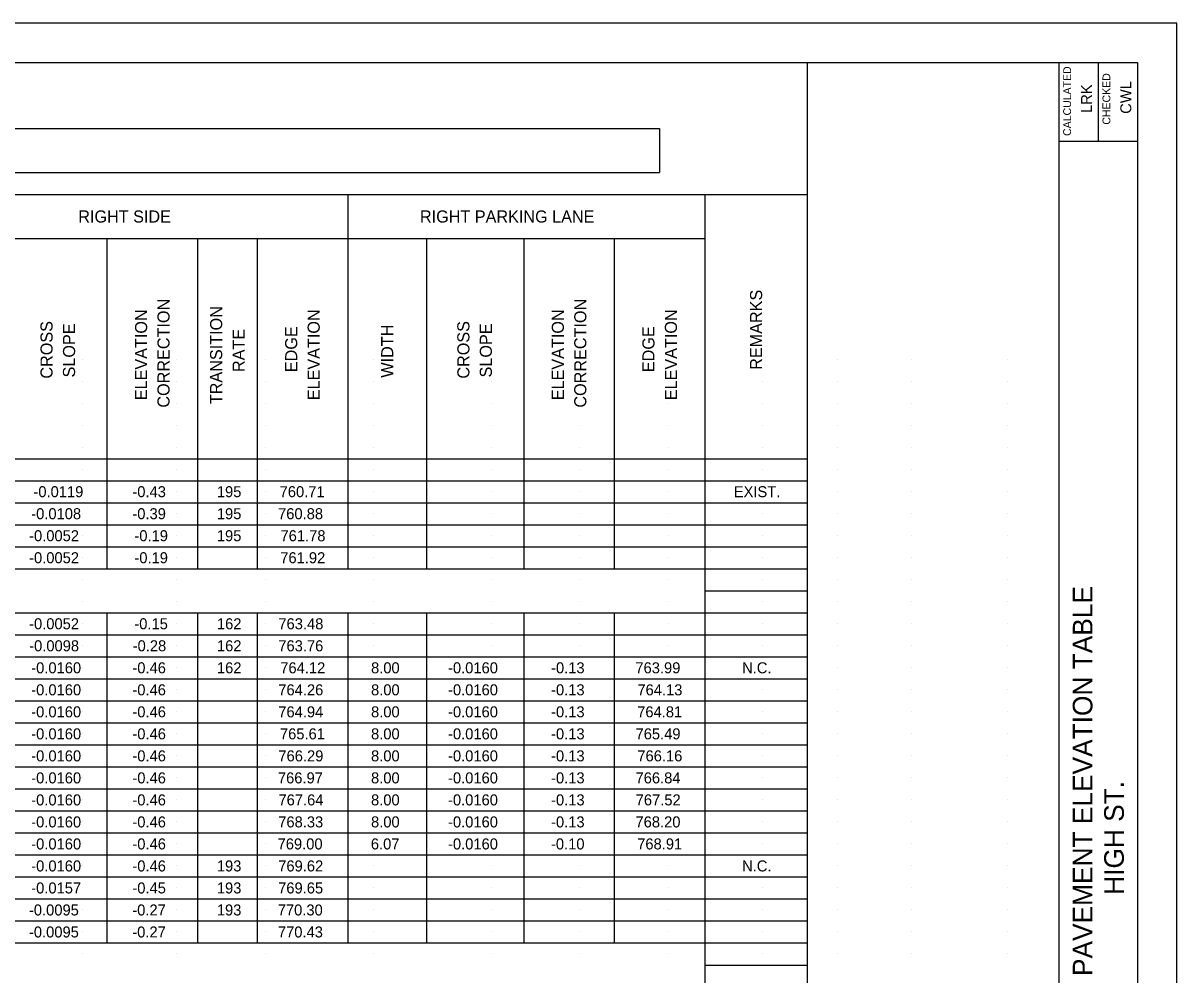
# Model space of a CAD drawing. Extents: x -15.4 to 18.6, y -12.6 to 9.4.
# Drawn here: x 3.96 to 18.64, y -2.72 to 9.39 of the extents above; entities that cross this region are included whole.
import ezdxf

# ---------------------------------------------------------------- set-up
doc = ezdxf.new("R2010")
doc.units = 0
for name, color, linetype in [('SH_Border', 7, 'Continuous'), ('SH_Cut_Line', 7, 'Continuous'), ('SH_Data', 7, 'Continuous'), ('SH_Text', 7, 'Continuous')]:
    doc.layers.add(name, color=color, linetype=linetype)

msp = doc.modelspace()

# ---------------------------------------------------------------- linework, layer by layer
at = {"layer": 'SH_Border'}
for p, q in [((17.143, -12.112), (17.143, 8.888)), ((17.643, 8.888), (17.643, 7.888)), ((17.143, 7.888), (18.143, 7.888))]:
    msp.add_line(p, q, dxfattribs=at)
msp.add_lwpolyline([(-13.357, 8.888), (18.143, 8.888), (18.143, -12.112), (-13.357, -12.112)], close=True, dxfattribs=at)
at = {"layer": 'SH_Cut_Line'}
msp.add_lwpolyline([(-15.357, -12.612), (18.643, -12.612), (18.643, 9.388), (-15.357, 9.388)], close=True, dxfattribs=at)
at = {"layer": 'SH_Data'}
for p, q in [((-10.059, 8.888), (13.939, 8.888)), ((13.939, 8.888), (13.939, -6.232)), ((-8.906, 8.048), (12.061, 8.048)), ((12.061, 8.048), (12.061, 7.488)), ((-8.906, 7.488), (12.061, 7.488)), ((-10.059, 7.208), (13.939, 7.208)), ((8.092, 7.208), (8.092, 2.448)), ((12.637, 7.208), (12.637, -6.232)), ((-10.059, 6.648), (12.637, 6.648)), ((5.028, 6.648), (5.028, 2.448)), ((6.181, 6.648), (6.181, 2.448)), ((6.939, 6.648), (6.939, 2.448)), ((9.096, 6.648), (9.096, 2.448)), ((10.332, 6.648), (10.332, 2.448)), ((11.484, 6.648), (11.484, 2.448)), ((4.718, 5.108), (4.718, 5.108)), ((5.918, 5.108), (5.918, 5.108)), ((7.043, 5.108), (7.043, 5.108)), ((8.418, 5.108), (8.418, 5.108)), ((9.918, 5.108), (9.918, 5.108)), ((11.043, 5.108), (11.043, 5.108)), ((12.168, 5.108), (12.168, 5.108)), ((13.368, 5.108), (13.368, 5.108)), ((14.318, 5.108), (14.318, 5.108)), ((15.268, 5.108), (15.268, 5.108)), ((16.493, 5.108), (16.493, 5.108)), ((4.718, 4.828), (4.718, 4.828)), ((5.918, 4.828), (5.918, 4.828)), ((7.043, 4.828), (7.043, 4.828)), ((8.418, 4.828), (8.418, 4.828)), ((9.918, 4.828), (9.918, 4.828)), ((11.043, 4.828), (11.043, 4.828)), ((12.168, 4.828), (12.168, 4.828)), ((13.368, 4.828), (13.368, 4.828)), ((14.318, 4.828), (14.318, 4.828)), ((15.268, 4.828), (15.268, 4.828)), ((16.493, 4.828), (16.493, 4.828)), ((4.718, 4.548), (4.718, 4.548)), ((5.918, 4.548), (5.918, 4.548)), ((7.043, 4.548), (7.043, 4.548)), ((8.418, 4.548), (8.418, 4.548)), ((9.918, 4.548), (9.918, 4.548)), ((11.043, 4.548), (11.043, 4.548)), ((12.168, 4.548), (12.168, 4.548)), ((13.368, 4.548), (13.368, 4.548)), ((14.318, 4.548), (14.318, 4.548)), ((15.268, 4.548), (15.268, 4.548)), ((16.493, 4.548), (16.493, 4.548)), ((4.718, 4.268), (4.718, 4.268)), ((5.918, 4.268), (5.918, 4.268)), ((7.043, 4.268), (7.043, 4.268)), ((8.418, 4.268), (8.418, 4.268)), ((9.918, 4.268), (9.918, 4.268)), ((11.043, 4.268), (11.043, 4.268)), ((12.168, 4.268), (12.168, 4.268)), ((13.368, 4.268), (13.368, 4.268)), ((14.318, 4.268), (14.318, 4.268)), ((15.268, 4.268), (15.268, 4.268)), ((16.493, 4.268), (16.493, 4.268)), ((4.718, 3.988), (4.718, 3.988)), ((5.918, 3.988), (5.918, 3.988)), ((7.043, 3.988), (7.043, 3.988)), ((8.418, 3.988), (8.418, 3.988)), ((9.918, 3.988), (9.918, 3.988)), ((11.043, 3.988), (11.043, 3.988)), ((12.168, 3.988), (12.168, 3.988)), ((13.368, 3.988), (13.368, 3.988)), ((14.318, 3.988), (14.318, 3.988)), ((15.268, 3.988), (15.268, 3.988)), ((16.493, 3.988), (16.493, 3.988)), ((-10.059, 3.848), (13.939, 3.848)), ((4.718, 3.708), (4.718, 3.708)), ((5.918, 3.708), (5.918, 3.708)), ((7.043, 3.708), (7.043, 3.708)), ((8.418, 3.708), (8.418, 3.708)), ((9.918, 3.708), (9.918, 3.708)), ((11.043, 3.708), (11.043, 3.708)), ((12.168, 3.708), (12.168, 3.708)), ((13.368, 3.708), (13.368, 3.708)), ((14.318, 3.708), (14.318, 3.708)), ((15.268, 3.708), (15.268, 3.708)), ((16.493, 3.708), (16.493, 3.708)), ((-10.059, 3.568), (13.939, 3.568)), ((4.718, 3.428), (4.718, 3.428)), ((5.918, 3.428), (5.918, 3.428)), ((7.043, 3.428), (7.043, 3.428)), ((8.418, 3.428), (8.418, 3.428)), ((9.918, 3.428), (9.918, 3.428)), ((11.043, 3.428), (11.043, 3.428)), ((12.168, 3.428), (12.168, 3.428)), ((13.368, 3.428), (13.368, 3.428)), ((14.318, 3.428), (14.318, 3.428)), ((15.268, 3.428), (15.268, 3.428)), ((16.493, 3.428), (16.493, 3.428)), ((-10.059, 3.288), (13.939, 3.288)), ((4.718, 3.148), (4.718, 3.148)), ((5.918, 3.148), (5.918, 3.148)), ((7.043, 3.148), (7.043, 3.148)), ((8.418, 3.148), (8.418, 3.148)), ((9.918, 3.148), (9.918, 3.148)), ((11.043, 3.148), (11.043, 3.148)), ((12.168, 3.148), (12.168, 3.148)), ((13.368, 3.148), (13.368, 3.148)), ((14.318, 3.148), (14.318, 3.148)), ((15.268, 3.148), (15.268, 3.148)), ((16.493, 3.148), (16.493, 3.148)), ((-10.059, 3.008), (13.939, 3.008)), ((4.718, 2.868), (4.718, 2.868)), ((5.918, 2.868), (5.918, 2.868)), ((7.043, 2.868), (7.043, 2.868)), ((8.418, 2.868), (8.418, 2.868)), ((9.918, 2.868), (9.918, 2.868)), ((11.043, 2.868), (11.043, 2.868)), ((12.168, 2.868), (12.168, 2.868)), ((13.368, 2.868), (13.368, 2.868)), ((14.318, 2.868), (14.318, 2.868)), ((15.268, 2.868), (15.268, 2.868)), ((16.493, 2.868), (16.493, 2.868)), ((-10.059, 2.728), (13.939, 2.728)), ((4.718, 2.588), (4.718, 2.588)), ((5.918, 2.588), (5.918, 2.588)), ((7.043, 2.588), (7.043, 2.588)), ((8.418, 2.588), (8.418, 2.588)), ((9.918, 2.588), (9.918, 2.588)), ((11.043, 2.588), (11.043, 2.588)), ((12.168, 2.588), (12.168, 2.588)), ((13.368, 2.588), (13.368, 2.588)), ((14.318, 2.588), (14.318, 2.588)), ((15.268, 2.588), (15.268, 2.588)), ((16.493, 2.588), (16.493, 2.588)), ((-10.059, 2.448), (13.939, 2.448)), ((4.718, 2.308), (4.718, 2.308)), ((5.918, 2.308), (5.918, 2.308)), ((7.043, 2.308), (7.043, 2.308)), ((8.418, 2.308), (8.418, 2.308)), ((9.918, 2.308), (9.918, 2.308)), ((11.043, 2.308), (11.043, 2.308)), ((12.168, 2.308), (12.168, 2.308)), ((13.368, 2.308), (13.368, 2.308)), ((14.318, 2.308), (14.318, 2.308)), ((15.268, 2.308), (15.268, 2.308)), ((16.493, 2.308), (16.493, 2.308)), ((12.637, 2.168), (13.939, 2.168)), ((4.718, 2.028), (4.718, 2.028)), ((5.918, 2.028), (5.918, 2.028)), ((7.043, 2.028), (7.043, 2.028)), ((8.418, 2.028), (8.418, 2.028)), ((9.918, 2.028), (9.918, 2.028)), ((11.043, 2.028), (11.043, 2.028)), ((12.168, 2.028), (12.168, 2.028)), ((13.368, 2.028), (13.368, 2.028)), ((14.318, 2.028), (14.318, 2.028)), ((15.268, 2.028), (15.268, 2.028)), ((16.493, 2.028), (16.493, 2.028)), ((-10.059, 1.888), (13.939, 1.888)), ((5.028, 1.888), (5.028, -2.312)), ((6.181, 1.888), (6.181, -2.312)), ((6.939, 1.888), (6.939, -2.312)), ((8.092, 1.888), (8.092, -2.312)), ((9.096, 1.888), (9.096, -2.312)), ((10.332, 1.888), (10.332, -2.312)), ((11.484, 1.888), (11.484, -2.312)), ((4.718, 1.748), (4.718, 1.748)), ((5.918, 1.748), (5.918, 1.748)), ((7.043, 1.748), (7.043, 1.748)), ((8.418, 1.748), (8.418, 1.748)), ((9.918, 1.748), (9.918, 1.748)), ((11.043, 1.748), (11.043, 1.748)), ((12.168, 1.748), (12.168, 1.748)), ((13.368, 1.748), (13.368, 1.748)), ((14.318, 1.748), (14.318, 1.748)), ((15.268, 1.748), (15.268, 1.748)), ((16.493, 1.748), (16.493, 1.748)), ((-10.059, 1.608), (13.939, 1.608)), ((-10.059, 1.328), (13.939, 1.328)), ((4.718, 1.468), (4.718, 1.468)), ((5.918, 1.468), (5.918, 1.468)), ((7.043, 1.468), (7.043, 1.468)), ((8.418, 1.468), (8.418, 1.468)), ((9.918, 1.468), (9.918, 1.468)), ((11.043, 1.468), (11.043, 1.468)), ((12.168, 1.468), (12.168, 1.468)), ((13.368, 1.468), (13.368, 1.468)), ((14.318, 1.468), (14.318, 1.468)), ((15.268, 1.468), (15.268, 1.468)), ((16.493, 1.468), (16.493, 1.468)), ((4.718, 1.188), (4.718, 1.188)), ((5.918, 1.188), (5.918, 1.188)), ((7.043, 1.188), (7.043, 1.188)), ((8.418, 1.188), (8.418, 1.188)), ((9.918, 1.188), (9.918, 1.188)), ((11.043, 1.188), (11.043, 1.188)), ((12.168, 1.188), (12.168, 1.188)), ((13.368, 1.188), (13.368, 1.188)), ((14.318, 1.188), (14.318, 1.188)), ((15.268, 1.188), (15.268, 1.188)), ((16.493, 1.188), (16.493, 1.188)), ((-10.059, 1.048), (13.939, 1.048)), ((4.718, 0.908), (4.718, 0.908)), ((5.918, 0.908), (5.918, 0.908)), ((7.043, 0.908), (7.043, 0.908)), ((8.418, 0.908), (8.418, 0.908)), ((9.918, 0.908), (9.918, 0.908)), ((11.043, 0.908), (11.043, 0.908)), ((12.168, 0.908), (12.168, 0.908)), ((13.368, 0.908), (13.368, 0.908)), ((14.318, 0.908), (14.318, 0.908)), ((15.268, 0.908), (15.268, 0.908)), ((16.493, 0.908), (16.493, 0.908)), ((-10.059, 0.768), (13.939, 0.768)), ((4.718, 0.628), (4.718, 0.628)), ((5.918, 0.628), (5.918, 0.628)), ((7.043, 0.628), (7.043, 0.628)), ((8.418, 0.628), (8.418, 0.628)), ((9.918, 0.628), (9.918, 0.628)), ((11.043, 0.628), (11.043, 0.628)), ((12.168, 0.628), (12.168, 0.628)), ((13.368, 0.628), (13.368, 0.628)), ((14.318, 0.628), (14.318, 0.628)), ((15.268, 0.628), (15.268, 0.628)), ((16.493, 0.628), (16.493, 0.628)), ((-10.059, 0.488), (13.939, 0.488)), ((4.718, 0.348), (4.718, 0.348)), ((5.918, 0.348), (5.918, 0.348)), ((7.043, 0.348), (7.043, 0.348)), ((8.418, 0.348), (8.418, 0.348)), ((9.918, 0.348), (9.918, 0.348)), ((11.043, 0.348), (11.043, 0.348)), ((12.168, 0.348), (12.168, 0.348)), ((13.368, 0.348), (13.368, 0.348)), ((14.318, 0.348), (14.318, 0.348)), ((15.268, 0.348), (15.268, 0.348)), ((16.493, 0.348), (16.493, 0.348)), ((-10.059, 0.208), (13.939, 0.208)), ((4.718, 0.068), (4.718, 0.068)), ((5.918, 0.068), (5.918, 0.068)), ((7.043, 0.068), (7.043, 0.068)), ((8.418, 0.068), (8.418, 0.068)), ((9.918, 0.068), (9.918, 0.068)), ((11.043, 0.068), (11.043, 0.068)), ((12.168, 0.068), (12.168, 0.068)), ((13.368, 0.068), (13.368, 0.068)), ((14.318, 0.068), (14.318, 0.068)), ((15.268, 0.068), (15.268, 0.068)), ((16.493, 0.068), (16.493, 0.068)), ((-10.059, -0.072), (13.939, -0.072)), ((4.718, -0.212), (4.718, -0.212)), ((5.918, -0.212), (5.918, -0.212)), ((7.043, -0.212), (7.043, -0.212)), ((8.418, -0.212), (8.418, -0.212)), ((9.918, -0.212), (9.918, -0.212)), ((11.043, -0.212), (11.043, -0.212)), ((12.168, -0.212), (12.168, -0.212)), ((13.368, -0.212), (13.368, -0.212)), ((14.318, -0.212), (14.318, -0.212)), ((15.268, -0.212), (15.268, -0.212)), ((16.493, -0.212), (16.493, -0.212)), ((-10.059, -0.352), (13.939, -0.352)), ((4.718, -0.492), (4.718, -0.492)), ((5.918, -0.492), (5.918, -0.492)), ((7.043, -0.492), (7.043, -0.492)), ((8.418, -0.492), (8.418, -0.492)), ((9.918, -0.492), (9.918, -0.492)), ((11.043, -0.492), (11.043, -0.492)), ((12.168, -0.492), (12.168, -0.492)), ((13.368, -0.492), (13.368, -0.492)), ((14.318, -0.492), (14.318, -0.492)), ((15.268, -0.492), (15.268, -0.492)), ((16.493, -0.492), (16.493, -0.492)), ((-10.059, -0.632), (13.939, -0.632)), ((4.718, -0.772), (4.718, -0.772)), ((5.918, -0.772), (5.918, -0.772)), ((7.043, -0.772), (7.043, -0.772)), ((8.418, -0.772), (8.418, -0.772)), ((9.918, -0.772), (9.918, -0.772)), ((11.043, -0.772), (11.043, -0.772)), ((12.168, -0.772), (12.168, -0.772)), ((13.368, -0.772), (13.368, -0.772)), ((14.318, -0.772), (14.318, -0.772)), ((15.268, -0.772), (15.268, -0.772)), ((16.493, -0.772), (16.493, -0.772)), ((-10.059, -0.912), (13.939, -0.912)), ((4.718, -1.052), (4.718, -1.052)), ((5.918, -1.052), (5.918, -1.052)), ((7.043, -1.052), (7.043, -1.052)), ((8.418, -1.052), (8.418, -1.052)), ((9.918, -1.052), (9.918, -1.052)), ((11.043, -1.052), (11.043, -1.052)), ((12.168, -1.052), (12.168, -1.052)), ((13.368, -1.052), (13.368, -1.052)), ((14.318, -1.052), (14.318, -1.052)), ((15.268, -1.052), (15.268, -1.052)), ((16.493, -1.052), (16.493, -1.052)), ((-10.059, -1.192), (13.939, -1.192)), ((4.718, -1.332), (4.718, -1.332)), ((5.918, -1.332), (5.918, -1.332)), ((7.043, -1.332), (7.043, -1.332)), ((8.418, -1.332), (8.418, -1.332)), ((9.918, -1.332), (9.918, -1.332)), ((11.043, -1.332), (11.043, -1.332)), ((12.168, -1.332), (12.168, -1.332)), ((13.368, -1.332), (13.368, -1.332)), ((14.318, -1.332), (14.318, -1.332)), ((15.268, -1.332), (15.268, -1.332)), ((16.493, -1.332), (16.493, -1.332)), ((-10.059, -1.472), (13.939, -1.472)), ((4.718, -1.612), (4.718, -1.612)), ((5.918, -1.612), (5.918, -1.612)), ((7.043, -1.612), (7.043, -1.612)), ((8.418, -1.612), (8.418, -1.612)), ((9.918, -1.612), (9.918, -1.612)), ((11.043, -1.612), (11.043, -1.612)), ((12.168, -1.612), (12.168, -1.612)), ((13.368, -1.612), (13.368, -1.612)), ((14.318, -1.612), (14.318, -1.612)), ((15.268, -1.612), (15.268, -1.612)), ((16.493, -1.612), (16.493, -1.612)), ((-10.059, -1.752), (13.939, -1.752)), ((4.718, -1.892), (4.718, -1.892)), ((5.918, -1.892), (5.918, -1.892)), ((7.043, -1.892), (7.043, -1.892)), ((8.418, -1.892), (8.418, -1.892)), ((9.918, -1.892), (9.918, -1.892)), ((11.043, -1.892), (11.043, -1.892)), ((12.168, -1.892), (12.168, -1.892)), ((13.368, -1.892), (13.368, -1.892)), ((14.318, -1.892), (14.318, -1.892)), ((15.268, -1.892), (15.268, -1.892)), ((16.493, -1.892), (16.493, -1.892)), ((-10.059, -2.032), (13.939, -2.032)), ((4.718, -2.172), (4.718, -2.172)), ((5.918, -2.172), (5.918, -2.172)), ((7.043, -2.172), (7.043, -2.172)), ((8.418, -2.172), (8.418, -2.172)), ((9.918, -2.172), (9.918, -2.172)), ((11.043, -2.172), (11.043, -2.172)), ((12.168, -2.172), (12.168, -2.172)), ((13.368, -2.172), (13.368, -2.172)), ((14.318, -2.172), (14.318, -2.172)), ((15.268, -2.172), (15.268, -2.172)), ((16.493, -2.172), (16.493, -2.172)), ((-10.059, -2.312), (13.939, -2.312)), ((4.718, -2.452), (4.718, -2.452)), ((5.918, -2.452), (5.918, -2.452)), ((7.043, -2.452), (7.043, -2.452)), ((8.418, -2.452), (8.418, -2.452)), ((9.918, -2.452), (9.918, -2.452)), ((11.043, -2.452), (11.043, -2.452)), ((12.168, -2.452), (12.168, -2.452)), ((13.368, -2.452), (13.368, -2.452)), ((14.318, -2.452), (14.318, -2.452)), ((15.268, -2.452), (15.268, -2.452)), ((16.493, -2.452), (16.493, -2.452)), ((12.637, -2.592), (13.939, -2.592))]:
    msp.add_line(p, q, dxfattribs=at)

# ---------------------------------------------------------------- texts
for s, height, p in [('CALCULATED', 0.1, (17.296, 7.953)), ('CHECKED', 0.1, (17.796, 8.096)), ('LRK', 0.14, (17.563, 8.245)), ('CWL', 0.14, (18.063, 8.234)), ('PAVEMENT ELEVATION TABLE', 0.25, (17.568, -2.732)), ('              HIGH ST.              ', 0.25, (17.968, -3))]:
    msp.add_text(s, height=height, rotation=90, dxfattribs=at).set_placement(p)
at = {"layer": 'SH_Text'}
for s, height, p in [('RIGHT SIDE ', 0.154, (4.663, 6.851)), ('RIGHT PARKING LANE', 0.154, (9.011, 6.851)), ('-0.0119', 0.14, (4.092, 3.358)), ('-0.43', 0.14, (5.351, 3.358)), ('195', 0.14, (6.426, 3.358)), ('760.71', 0.14, (7.225, 3.358)), ('EXIST.', 0.14, (13.004, 3.358)), ('-0.0108', 0.14, (4.064, 3.078)), ('-0.39', 0.14, (5.351, 3.078)), ('195', 0.14, (6.426, 3.078)), ('760.88', 0.14, (7.205, 3.078)), ('-0.0052', 0.14, (4.037, 2.798)), ('-0.19', 0.14, (5.377, 2.798)), ('195', 0.14, (6.426, 2.798)), ('761.78', 0.14, (7.236, 2.798)), ('-0.0052', 0.14, (4.037, 2.518)), ('-0.19', 0.14, (5.377, 2.518)), ('761.92', 0.14, (7.233, 2.518)), ('-0.0052', 0.14, (4.037, 1.678)), ('-0.15', 0.14, (5.376, 1.678)), ('162', 0.14, (6.427, 1.678)), ('763.48', 0.14, (7.209, 1.678)), ('-0.0098', 0.14, (4.038, 1.398)), ('-0.28', 0.14, (5.355, 1.398)), ('162', 0.14, (6.427, 1.398)), ('763.76', 0.14, (7.208, 1.398)), ('-0.0160', 0.14, (4.064, 1.118)), ('-0.46', 0.14, (5.351, 1.118)), ('162', 0.14, (6.427, 1.118)), ('764.12', 0.14, (7.233, 1.118)), ('8.00', 0.14, (8.388, 1.118)), ('-0.0160', 0.14, (9.368, 1.118)), ('-0.13', 0.14, (10.679, 1.118)), ('763.99', 0.14, (11.752, 1.118)), ('N.C.', 0.14, (13.11, 1.118)), ('-0.0160', 0.14, (4.064, 0.838)), ('-0.46', 0.14, (5.351, 0.838)), ('764.26', 0.14, (7.208, 0.838)), ('8.00', 0.14, (8.388, 0.838)), ('-0.0160', 0.14, (9.368, 0.838)), ('-0.13', 0.14, (10.679, 0.838)), ('764.13', 0.14, (11.778, 0.838)), ('-0.0160', 0.14, (4.064, 0.558)), ('-0.46', 0.14, (5.351, 0.558)), ('764.94', 0.14, (7.208, 0.558)), ('8.00', 0.14, (8.388, 0.558)), ('-0.0160', 0.14, (9.368, 0.558)), ('-0.13', 0.14, (10.679, 0.558)), ('764.81', 0.14, (11.775, 0.558)), ('-0.0160', 0.14, (4.064, 0.278)), ('-0.46', 0.14, (5.351, 0.278)), ('765.61', 0.14, (7.229, 0.278)), ('8.00', 0.14, (8.388, 0.278)), ('-0.0160', 0.14, (9.368, 0.278)), ('-0.13', 0.14, (10.679, 0.278)), ('765.49', 0.14, (11.754, 0.278)), ('-0.0160', 0.14, (4.064, -0.002)), ('-0.46', 0.14, (5.351, -0.002)), ('766.29', 0.14, (7.209, -0.002)), ('8.00', 0.14, (8.388, -0.002)), ('-0.0160', 0.14, (9.368, -0.002)), ('-0.13', 0.14, (10.679, -0.002)), ('766.16', 0.14, (11.777, -0.002)), ('-0.0160', 0.14, (4.064, -0.282)), ('-0.46', 0.14, (5.351, -0.282)), ('766.97', 0.14, (7.203, -0.282)), ('8.00', 0.14, (8.388, -0.282)), ('-0.0160', 0.14, (9.368, -0.282)), ('-0.13', 0.14, (10.679, -0.282)), ('766.84', 0.14, (11.754, -0.282)), ('-0.0160', 0.14, (4.064, -0.562)), ('-0.46', 0.14, (5.351, -0.562)), ('767.64', 0.14, (7.21, -0.562)), ('8.00', 0.14, (8.388, -0.562)), ('-0.0160', 0.14, (9.368, -0.562)), ('-0.13', 0.14, (10.679, -0.562)), ('767.52', 0.14, (11.756, -0.562)), ('-0.0160', 0.14, (4.064, -0.842)), ('-0.46', 0.14, (5.351, -0.842)), ('768.33', 0.14, (7.207, -0.842)), ('8.00', 0.14, (8.388, -0.842)), ('-0.0160', 0.14, (9.368, -0.842)), ('-0.13', 0.14, (10.679, -0.842)), ('768.20', 0.14, (11.753, -0.842)), ('-0.0160', 0.14, (4.064, -1.122)), ('-0.46', 0.14, (5.351, -1.122)), ('769.00', 0.14, (7.199, -1.122)), ('6.07', 0.14, (8.386, -1.122)), ('-0.0160', 0.14, (9.368, -1.122)), ('-0.10', 0.14, (10.678, -1.122)), ('768.91', 0.14, (11.775, -1.122)), ('-0.0160', 0.14, (4.064, -1.402)), ('-0.46', 0.14, (5.351, -1.402)), ('193', 0.14, (6.426, -1.402)), ('769.62', 0.14, (7.207, -1.402)), ('N.C.', 0.14, (13.11, -1.402)), ('-0.0157', 0.14, (4.064, -1.682)), ('-0.45', 0.14, (5.351, -1.682)), ('193', 0.14, (6.426, -1.682)), ('769.65', 0.14, (7.206, -1.682)), ('-0.0095', 0.14, (4.035, -1.962)), ('-0.27', 0.14, (5.35, -1.962)), ('193', 0.14, (6.426, -1.962)), ('770.30', 0.14, (7.201, -1.962)), ('-0.0095', 0.14, (4.035, -2.242)), ('-0.27', 0.14, (5.35, -2.242)), ('770.43', 0.14, (7.203, -2.242))]:
    msp.add_text(s, height=height, dxfattribs=at).set_placement(p)
for s, p in [('REMARKS', (13.365, 4.978)), ('ELEVATION', (5.539, 4.591)), ('CORRECTION', (5.824, 4.497)), ('TRANSITION', (6.494, 4.541)), ('ELEVATION', (7.735, 4.591)), ('ELEVATION', (10.842, 4.591)), ('CORRECTION', (11.128, 4.497)), ('ELEVATION', (12.281, 4.591)), ('CROSS', (4.336, 4.866)), ('CROSS', (9.64, 4.866)), ('SLOPE', (4.622, 4.881)), ('RATE', (6.78, 4.95)), ('EDGE', (7.449, 4.948)), ('WIDTH', (8.671, 4.878)), ('SLOPE', (9.926, 4.881)), ('EDGE', (11.995, 4.948))]:
    msp.add_text(s, height=0.154, rotation=90, dxfattribs=at).set_placement(p)

doc.saveas('drawing.dxf')
